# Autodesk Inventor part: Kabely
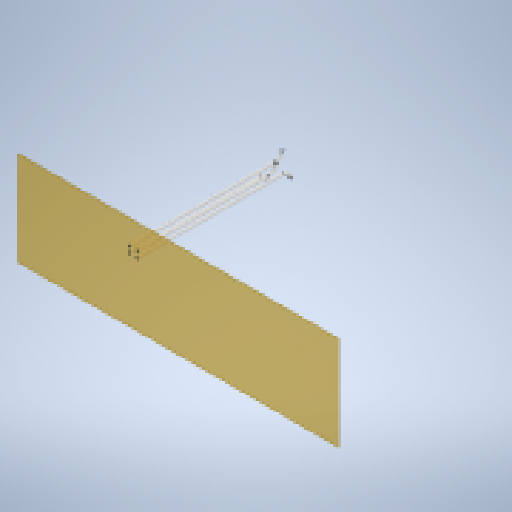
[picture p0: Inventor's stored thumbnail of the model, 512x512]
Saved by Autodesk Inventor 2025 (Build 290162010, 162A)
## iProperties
Created: 2025-05
Part Number: Kabely
Material: Všeobecné
Document SubType Name: Modeling
Designer: p2_kadlcik
Density: 1 g/cm^3
Appearance: Výchozí
Author: p2_kadlcik
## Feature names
1. Tažení1
2. Tažení2
3. Tažení3
4. Tažení4
## Parameters: d1 = 0, d2 = 0, d3 = 4 mm, d4 = 8 mm, d5 = 4 mm, d6 = 8 mm, d7 = 4 mm, d8 = 4 mm, d10 = 0, d11 = 0, d12 = 4 mm, d13 = 4 mm, d15 = 0, d16 = 0, d17 = 4 mm, d18 = 0, d19 = 0
